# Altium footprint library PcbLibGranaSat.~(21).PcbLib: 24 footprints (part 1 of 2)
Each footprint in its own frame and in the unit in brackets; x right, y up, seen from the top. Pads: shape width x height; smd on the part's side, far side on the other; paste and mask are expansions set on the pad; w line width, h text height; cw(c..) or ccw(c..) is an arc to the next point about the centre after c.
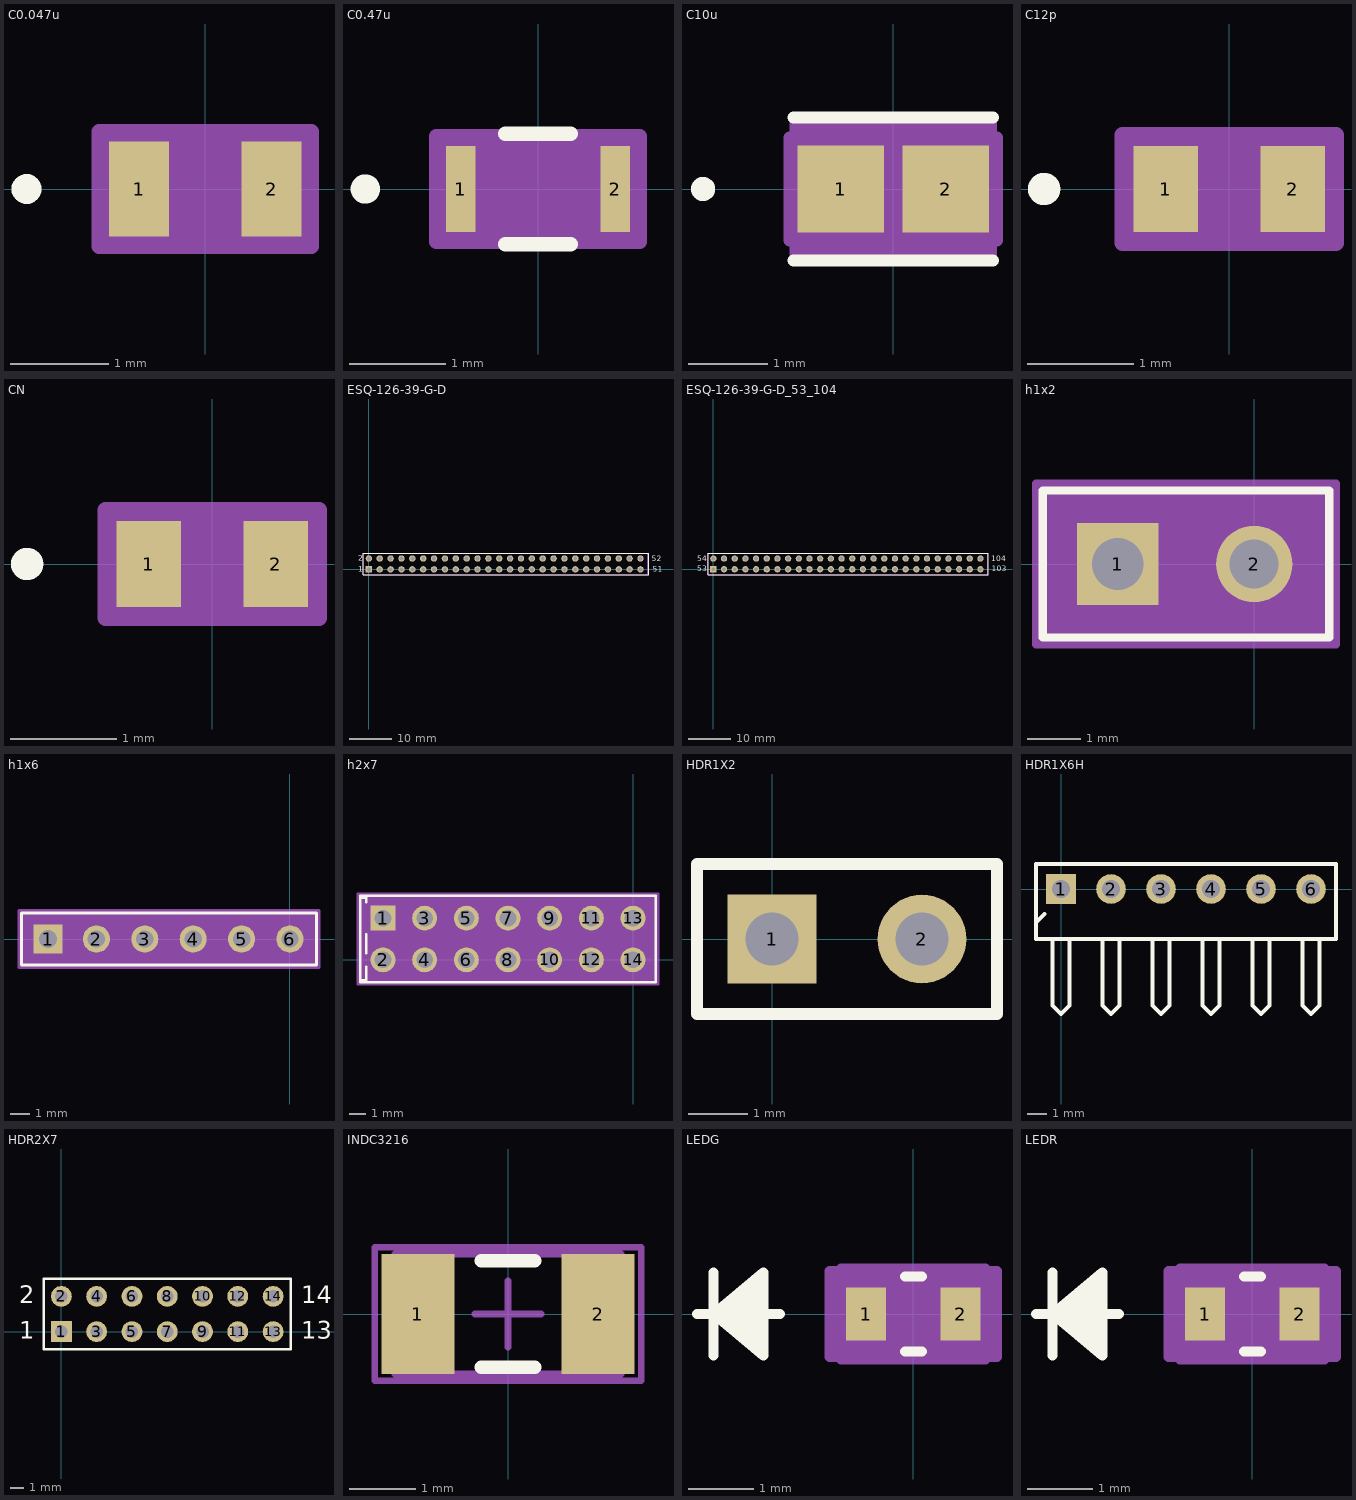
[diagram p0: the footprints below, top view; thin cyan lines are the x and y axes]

## C0.047u [mil]
pads (2):
  rect 24x38 smd paste+0 mask+0: 1(-26.5,0) 2(26.5,0)
Top Overlay:
  circle w6: c-71.5,0 r3
Mechanical 13:
  circle w0: c-21.5,0 r3
  lines w1: -34.5,-19 -34.5,19 ; -34.5,-19 34.5,-19 ; -34.5,-19 -14.5,-19 -14.5,19 -34.5,19 ; -34.5,-19 -34.5,19 ; -34.5,19 34.5,19 ; 34.5,-19 34.5,19 ; 34.5,-19 34.5,19 ; 34.5,-19 14.5,-19 14.5,19 34.5,19
Mechanical 15:
  region: 42.5,-23 -42.5,-23 -42.5,23 42.5,23
  lines w6: -42.5,-23 42.5,-23 42.5,23 -42.5,23 -42.5,-23
3D body: height 10, standoff 0, extent 0,0 10,10
3D body "0603-L.stp": height 35, standoff 0, extent -34.49,-19.01 34.49,19.02

## C0.47u [mil]
pads (2):
  rect 12x35 smd paste+0 mask+0: 1(-31.5,0) 2(31.5,0)
Top Overlay:
  circle w6: c-70.5,0 r3
  lines w6: -13.39,-22.5 13.39,-22.5 ; -13.39,22.5 13.39,22.5
Mechanical 13:
  circle w0: c-26.5,0 r3
  lines w1: -33.5,-17.5 -33.5,17.5 ; -33.5,-17.5 33.5,-17.5 ; -33.5,-17.5 -25.5,-17.5 -25.5,17.5 -33.5,17.5 ; -33.5,-17.5 -33.5,17.5 ; -33.5,17.5 33.5,17.5 ; 33.5,-17.5 33.5,17.5 ; 33.5,-17.5 33.5,17.5 ; 33.5,-17.5 25.5,-17.5 25.5,17.5 33.5,17.5
Mechanical 15:
  region: 41.5,-21.5 -41.5,-21.5 -41.5,21.5 41.5,21.5
  lines w6: -41.5,-21.5 41.5,-21.5 41.5,21.5 -41.5,21.5 -41.5,-21.5
3D body: height 10, standoff 0, extent 0,0 10,10
3D body "CAP_1608-L.stp": height 35, standoff 0, extent -33.5,-17.48 33.51,17.48

## C10u [mil]
pads (2):
  rect 43x43 smd paste+0 mask+0: 1(-26,0) 2(26,0)
Top Overlay:
  circle w6: c-94.5,0 r3
  lines w6: -49.5,-35.5 49.5,-35.5 ; -49.5,35.5 49.5,35.5
Mechanical 13:
  circle w0: c-34.5,0 r3
  lines w1: -44.5,-30.5 -44.5,30.5 44.5,30.5 44.5,-30.5 -44.5,-30.5
Mechanical 15:
  region: -48.5,-25.5 -51.5,-25.5 -51.5,25.5 -48.5,25.5 -48.5,34.5 48.5,34.5 48.5,25.5 51.5,25.5 51.5,-25.5 48.5,-25.5 48.5,-34.5 -48.5,-34.5
  lines w6: -51.5,-25.5 -48.5,-25.5 -48.5,-34.5 48.5,-34.5 48.5,-25.5 51.5,-25.5 51.5,25.5 48.5,25.5 48.5,34.5 -48.5,34.5 -48.5,25.5 -51.5,25.5 -51.5,-25.5
3D body "TAJR-L.stp": height 49.02, standoff 0, extent -44.49,-30.51 44.49,30.52
3D body: height 10, standoff 0, extent 0,0 10,10

## C12p [mil]
pads (2):
  rect 24x32 smd paste+0 mask+0: 1(-23.5,0) 2(23.5,0)
Top Overlay:
  circle w6: c-68.5,0 r3
Mechanical 13:
  circle w0: c-18.5,0 r3
  lines w1: -31.5,-16 -31.5,16 ; -31.5,-16 31.5,-16 ; -31.5,-16 -11.5,-16 -11.5,16 -31.5,16 ; -31.5,-16 -31.5,16 ; -31.5,16 31.5,16 ; 31.5,-16 31.5,16 ; 31.5,-16 31.5,16 ; 31.5,-16 11.5,-16 11.5,16 31.5,16
Mechanical 15:
  region: 39.5,-20 -39.5,-20 -39.5,20 39.5,20
  lines w6: -39.5,-20 39.5,-20 39.5,20 -39.5,20 -39.5,-20
3D body "G-188-L.stp": height 35, standoff 0, extent -31.49,-15.98 31.5,15.99
3D body: height 10, standoff 0, extent 0,0 10,10

## CN [mil]
pads (2):
  rect 24x32 smd paste+0 mask+0: 1(-23.5,0) 2(23.5,0)
Top Overlay:
  circle w6: c-68.5,0 r3
Mechanical 13:
  circle w0: c-18.5,0 r3
  lines w1: -31.5,-16 -31.5,16 ; -31.5,-16 -11.5,-16 -11.5,16 -31.5,16 ; -31.5,-16 31.5,-16 ; -31.5,-16 -31.5,16 ; -31.5,16 31.5,16 ; 31.5,-16 11.5,-16 11.5,16 31.5,16 ; 31.5,-16 31.5,16 ; 31.5,-16 31.5,16
Mechanical 15:
  region: 39.5,-20 -39.5,-20 -39.5,20 39.5,20
  lines w6: -39.5,-20 -39.5,20 39.5,20 39.5,-20 -39.5,-20
3D body "G-188-L.stp": height 35, standoff 0, extent -31.49,-15.98 31.5,15.99
3D body: height 10, standoff 0, extent 0,0 10,10

## ESQ-126-39-G-D [mm] "Cubesat Connector; Header; 26x2 Position"
pads (52):
  rect 1.5x1.5 hole 0.9: 1(0,0)
  round 1.5 hole 0.9: 2(0,2.54) 3(2.54,0) 4(2.54,2.54) 5(5.08,0) 6(5.08,2.54) 7(7.62,0) 8(7.62,2.54) 9(10.16,0) 10(10.16,2.54) 11(12.7,0) 12(12.7,2.54) 13(15.24,0) 14(15.24,2.54) 15(17.78,0) 16(17.78,2.54) 17(20.32,0) 18(20.32,2.54) 19(22.86,0) 20(22.86,2.54) 21(25.4,0) 22(25.4,2.54) 23(27.94,0) 24(27.94,2.54) 25(30.48,0) 26(30.48,2.54) 27(33.02,0) 28(33.02,2.54) 29(35.56,0) 30(35.56,2.54) 31(38.1,0) 32(38.1,2.54) 33(40.64,0) 34(40.64,2.54) 35(43.18,0) 36(43.18,2.54) 37(45.72,0) 38(45.72,2.54) 39(48.26,0) 40(48.26,2.54) 41(50.8,0) 42(50.8,2.54) 43(53.34,0) 44(53.34,2.54) 45(55.88,0) 46(55.88,2.54) 47(58.42,0) 48(58.42,2.54) 49(60.96,0) 50(60.96,2.54) 51(63.5,0) 52(63.5,2.54)
Top Overlay:
  lines w0.2: -1.27,-1.27 -1.27,3.81 65.38,3.81 65.38,-1.27 -1.27,-1.27
  text "2" at -2.54,2.032 h1.27
  text "1" at -2.54,-0.508 h1.27
  text "51" at 66.319,-0.533 h1.27
  text "52" at 66.116,1.956 h1.27
Mechanical 16:
  lines w0.185: -1.3,-1.3 65.2,-1.3 65.2,3.8 -1.3,3.8 -1.3,-1.3
Mechanical 25:
  text "'.Designator'" at 20,0.6 h1.52
  text "1" at -0.2,-0.8 h1.52
  text "2" at -0.4,1.7 h1.52
3D body "ESQ-126-39-G-D.stp": height 10.51, standoff -12.73, extent -1.295,-1.295 65.253,3.785

## ESQ-126-39-G-D_53_104 [mm] "Cubesat Connector; Header; 26x2 Position"
pads (52):
  rect 1.5x1.5 hole 0.9: 53(0,0)
  round 1.5 hole 0.9: 54(0,2.54) 55(2.54,0) 56(2.54,2.54) 57(5.08,0) 58(5.08,2.54) 59(7.62,0) 60(7.62,2.54) 61(10.16,0) 62(10.16,2.54) 63(12.7,0) 64(12.7,2.54) 65(15.24,0) 66(15.24,2.54) 67(17.78,0) 68(17.78,2.54) 69(20.32,0) 70(20.32,2.54) 71(22.86,0) 72(22.86,2.54) 73(25.4,0) 74(25.4,2.54) 75(27.94,0) 76(27.94,2.54) 77(30.48,0) 78(30.48,2.54) 79(33.02,0) 80(33.02,2.54) 81(35.56,0) 82(35.56,2.54) 83(38.1,0) 84(38.1,2.54) 85(40.64,0) 86(40.64,2.54) 87(43.18,0) 88(43.18,2.54) 89(45.72,0) 90(45.72,2.54) 91(48.26,0) 92(48.26,2.54) 93(50.8,0) 94(50.8,2.54) 95(53.34,0) 96(53.34,2.54) 97(55.88,0) 98(55.88,2.54) 99(58.42,0) 100(58.42,2.54) 101(60.96,0) 102(60.96,2.54) 103(63.5,0) 104(63.5,2.54)
Top Overlay:
  lines w0.2: -1.27,-1.27 -1.27,3.81 65.38,3.81 65.38,-1.27 -1.27,-1.27
  text "54" at -3.81,1.905 h1.27
  text "53" at -3.886,-0.508 h1.27
  text "103" at 66.167,-0.483 h1.27
  text "104" at 66.116,1.956 h1.27
Mechanical 16:
  lines w0.185: -1.3,-1.3 65.2,-1.3 65.2,3.8 -1.3,3.8 -1.3,-1.3
Mechanical 25:
  text "'.Designator'" at 20,0.6 h1.52
  text "1" at -0.2,-0.8 h1.52
  text "2" at -0.4,1.7 h1.52
3D body "ESQ-126-39-G-D.stp": height 10.51, standoff -12.73, extent -1.295,-1.295 65.253,3.785

## h1x2 [mil]
pads (2):
  rect 60x60 hole 38 mask+0: 1(-100,0)
  round 56 hole 36 mask+0: 2(0,0)
Top Overlay:
  lines w6: -155,-54 -155,54 55,54 55,-54 -155,-54
Mechanical 13:
  circle w0: c-100,34 r10
  lines w1: -150,-49 -150,49 50,49 50,-49 -150,-49
Mechanical 15:
  region: 60,59 -160,59 -160,-59 60,-59
  lines w6: -160,-59 60,-59 60,59 -160,59 -160,-59
3D body "22-28-4025.stp": height 450, standoff -200, extent -150,-50 50,50
3D body: height 10, standoff 0, extent 0,0 10,10

## h1x6 [mil]
pads (6):
  rect 60x60 hole 38 mask+0: 1(-500,0)
  round 56 hole 36 mask+0: 2(-400,0) 3(-300,0) 4(-200,0) 5(-100,0) 6(0,0)
Top Overlay:
  lines w6: -555,-54 -555,54 55,54 55,-54 -555,-54
Mechanical 13:
  circle w0: c-500,34 r10
  lines w1: -550,-49 -550,49 50,49 50,-49 -550,-49
Mechanical 15:
  region: 60,59 -560,59 -560,-59 60,-59
  lines w6: -560,-59 60,-59 60,59 -560,59 -560,-59
3D body "22-28-4066.stp": height 450, standoff -200, extent -550,-50 50,50
3D body: height 10, standoff 0, extent 0,0 10,10

## h2x7 [mil]
pads (14):
  rect 60x60 hole 40 mask+0: 1(-600,100)
  round 60 hole 40 mask+0: 2(-600,0) 3(-500,100) 4(-500,0) 5(-400,100) 6(-400,0) 7(-300,100) 8(-300,0) 9(-200,100) 10(-200,0) 11(-100,100) 12(-100,0) 13(0,100) 14(0,0)
Top Overlay:
  lines w6: -650,-48.5 -640,-48.5 -640,-16.05 ; -650,148.5 -640,148.5 -640,138.46 ; -640,16.05 -640,61.54 ; -655,-53.5 -655,153.5 55,153.5 55,-53.5 -655,-53.5
Mechanical 13:
  lines w1: -650,-48.5 -650,148.5 ; -650,-48.5 50,-48.5 50,148.5 -650,148.5 ; -650,-48.5 -640,-48.5 -640,148.5 -650,148.5
Mechanical 15:
  region: 60,158.5 -660,158.5 -660,-58.5 60,-58.5
  lines w6: -660,-58.5 60,-58.5 60,158.5 -660,158.5 -660,-58.5
3D body "CON14_2X7_P100UM_HDR.stp": height 374.02, standoff -200, extent -650,-50 50,150
3D body: height 10, standoff 0, extent 0,0 10,10

## HDR1X2 [mm] "Connector; Header; 2 Position"
pads (2):
  rect 1.5x1.5 hole 0.9: 1(0,0)
  round 1.5 hole 0.9: 2(2.54,0)
Top Overlay:
  lines w0.2: -1.27,-1.27 -1.27,1.27 3.81,1.27 3.81,-1.27 -1.27,-1.27

## HDR1X6H [mm] "Connector; Header; 6 Position; Right Angle"
pads (6):
  rect 1.5x1.5 hole 0.9: 1(0,0)
  round 1.5 hole 0.9: 2(2.54,0) 3(5.08,0) 4(7.62,0) 5(10.16,0) 6(12.7,0)
Top Overlay:
  lines w0.2: -1.27,-1.693 -0.847,-1.27 ; -0.423,-2.54 -0.423,-5.927 0,-6.35 0.423,-5.927 0.423,-2.54 ; 2.117,-2.54 2.117,-5.927 2.54,-6.35 2.963,-5.927 2.963,-2.54 ; 4.657,-2.54 4.657,-5.927 5.08,-6.35 5.503,-5.927 5.503,-2.54 ; 7.197,-2.54 7.197,-5.927 7.62,-6.35 8.043,-5.927 8.043,-2.54 ; 9.737,-2.54 9.737,-5.927 10.16,-6.35 10.583,-5.927 10.583,-2.54 ; 12.277,-2.54 12.277,-5.927 12.7,-6.35 13.123,-5.927 13.123,-2.54 ; -1.27,-2.54 13.97,-2.54 13.97,1.27 -1.27,1.27 -1.27,-2.54

## HDR2X7 [mm] "Connector; Header; 7x2 Position"
pads (14):
  rect 1.5x1.5 hole 0.9: 1(0,0)
  round 1.5 hole 0.9: 2(0,2.54) 3(2.54,0) 4(2.54,2.54) 5(5.08,0) 6(5.08,2.54) 7(7.62,0) 8(7.62,2.54) 9(10.16,0) 10(10.16,2.54) 11(12.7,0) 12(12.7,2.54) 13(15.24,0) 14(15.24,2.54)
Top Overlay:
  lines w0.2: -1.27,-1.27 -1.27,3.81 16.51,3.81 16.51,-1.27 -1.27,-1.27
  text "2" at -3.048,2.032 h1.27
  text "1" at -3.048,-0.508 h1.27
  text "14" at 17.272,2.032 h1.27
  text "13" at 17.272,-0.508 h1.27

## INDC3216 [mm] "Chip Inductor, Body 3.2x1.6mm, IPC High Density"
height 0.55
pads (2):
  rect 1.1x1.8 smd: 1(-1.35,0) 2(1.35,0)
Top Overlay:
  lines w0.2: -0.4,-0.8 0.4,-0.8 ; -0.4,0.8 0.4,0.8
Mechanical 13:
  lines w0.1: -1.7,-0.9 1.7,-0.9 1.7,0.9 -1.7,0.9 -1.7,-0.9
Mechanical 15:
  lines w0.1: -0.5,0 0.5,0 ; 0,-0.5 0,0.5 ; -2,-1 2,-1 2,1 -2,1 -2,-1
3D body: height 0.55, standoff 0, extent -1.7,-0.9 1.7,0.9

## LEDG [mil]
pads (2):
  rect 24x32 smd paste+0 mask+0: 1(-28.5,0) 2(28.5,0)
Top Overlay:
  lines w6: -130.5,0 -80.5,0 ; -120.5,-25 -120.5,25 ; -90.5,-20 -120.5,0 ; -90.5,-15 -120.5,0 ; -90.5,-10 -120.5,0 ; -90.5,-5 -120.5,0 ; -90.5,5 -120.5,0 ; -90.5,10 -120.5,0 ; -90.5,15 -120.5,0 ; -90.5,20 -120.5,0 ; -5.13,-22.5 5.13,-22.5 ; -5.13,22.5 5.13,22.5 ; -120.5,0 -90.5,25 -90.5,-25 -120.5,0
Mechanical 13:
  lines w1: -130.5,0 -80.5,0 ; -120.5,-25 -120.5,25 ; -90.5,-20 -120.5,0 ; -90.5,-15 -120.5,0 ; -90.5,-10 -120.5,0 ; -90.5,-5 -120.5,0 ; -90.5,5 -120.5,0 ; -90.5,10 -120.5,0 ; -90.5,15 -120.5,0 ; -90.5,20 -120.5,0 ; -120.5,0 -90.5,25 -90.5,-25 -120.5,0 ; -33.5,-17.5 33.5,-17.5 33.5,17.5 -33.5,17.5 -33.5,-17.5
Mechanical 15:
  region: -43.5,-26 -50.5,-26 -50.5,26 -43.5,26 -43.5,27.5 43.5,27.5 43.5,26 50.5,26 50.5,-26 43.5,-26 43.5,-27.5 -43.5,-27.5
  lines w6: -50.5,-26 -50.5,26 -43.5,26 -43.5,27.5 43.5,27.5 43.5,26 50.5,26 50.5,-26 43.5,-26 43.5,-27.5 -43.5,-27.5 -43.5,-26 -50.5,-26
3D body: height 10, standoff 0, extent 0,0 10,10
3D body "LED_VISHAY_TLMX1100.stp": height 26.02, standoff 0, extent -33.5,-17.6 33.51,17.6

## LEDR [mil]
pads (2):
  rect 24x32 smd paste+0 mask+0: 1(-28.5,0) 2(28.5,0)
Top Overlay:
  lines w6: -130.5,0 -80.5,0 ; -120.5,-25 -120.5,25 ; -90.5,-20 -120.5,0 ; -90.5,-15 -120.5,0 ; -90.5,-10 -120.5,0 ; -90.5,-5 -120.5,0 ; -90.5,5 -120.5,0 ; -90.5,10 -120.5,0 ; -90.5,15 -120.5,0 ; -90.5,20 -120.5,0 ; -5.13,-22.5 5.13,-22.5 ; -5.13,22.5 5.13,22.5 ; -120.5,0 -90.5,25 -90.5,-25 -120.5,0
Mechanical 13:
  lines w1: -130.5,0 -80.5,0 ; -120.5,-25 -120.5,25 ; -90.5,-20 -120.5,0 ; -90.5,-15 -120.5,0 ; -90.5,-10 -120.5,0 ; -90.5,-5 -120.5,0 ; -90.5,5 -120.5,0 ; -90.5,10 -120.5,0 ; -90.5,15 -120.5,0 ; -90.5,20 -120.5,0 ; -120.5,0 -90.5,25 -90.5,-25 -120.5,0 ; -33.5,-17.5 33.5,-17.5 33.5,17.5 -33.5,17.5 -33.5,-17.5
Mechanical 15:
  region: -43.5,-26 -50.5,-26 -50.5,26 -43.5,26 -43.5,27.5 43.5,27.5 43.5,26 50.5,26 50.5,-26 43.5,-26 43.5,-27.5 -43.5,-27.5
  lines w6: -50.5,-26 -50.5,26 -43.5,26 -43.5,27.5 43.5,27.5 43.5,26 50.5,26 50.5,-26 43.5,-26 43.5,-27.5 -43.5,-27.5 -43.5,-26 -50.5,-26
3D body: height 10, standoff 0, extent 0,0 10,10
3D body "LED_VISHAY_TLMX1100.stp": height 26.02, standoff 0, extent -33.5,-17.59 33.51,17.6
